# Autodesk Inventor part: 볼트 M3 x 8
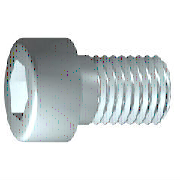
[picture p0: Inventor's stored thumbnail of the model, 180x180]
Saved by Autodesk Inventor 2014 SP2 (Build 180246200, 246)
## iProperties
Created: 2012-02
Part Number: 볼트 M3 x 8
Material: 스테인리스강
Description: 6각 소켓 머리 캡 나사
Document SubType Name: Modeling
Standard: ISO 4762
Designer: mduedu
Standard Revision: Fourth edition 2004-03-01
Standards Organization: ISO
Language: ko-KR
Size Designation: M3 x 8
Categories: <MemberInstance><Categories><Category DisplayName="조임쇠" InternalName="e4da775c-781d-43d5-af7c-5136215cf5a6" Mnemonic="FSTN"><Category DisplayName="볼트" InternalN
Density: 8.08 g/cm^3
Appearance: 반광택
IsCustomPart: 0
Author: mduedu
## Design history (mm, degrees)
sketch "스케치1"
  geometry: L1 (-0.867, 0)-(8, 0); L2 (8, 0)-(8, 1.5); L3 (8, 1.5)-(1.25, 1.5); L4 (1.25, 1.5)-(0.943, 1.5); L5 (0.943, 1.5)-(0, 1.5); L6 (0, 1.5)-(0, 2.75); L7 (0, 2.75)-(-3, 2.75); L8 (-3, 2.75)-(-3, 1.443); L9 (-3, 1.443)-(-1.7, 1.443); L10 (-1.7, 1.443)-(-0.867, 0); L11 (-5.2, 0)-(10.2, 0) reference; L12 (0, -0.55)-(0, 3.3) reference; L13 (1.25, 1.5)-(0, 1.5)
  constraints: 22 end point, 6 parallel, 2 collinear, 2 perpendicular, 1 horizontal, 1 point on line
  dimensions: "d1" = 6.75 distance from line of L3.end L2 (= GEL); "d2" = 0.30683 distance of L4.end L3.end (computed from GAL); "d3" = 3 distance between parallel lines of L8 L6 (= KOH); "d4" = 1.3 distance of L8.end L9.end (= INTI); "d5" = 60 deg angle of L10 L1; "d6" = 3 diameter of L3 L1 (= GD); "d7" = 3 diameter of L5 L1 (= BDM); "d8" = 2.88675 diameter of L9 L1 (= 1.1547 x SW); "d9" = 5.5 diameter of L7 L1 (= KOD); "d26" = 8 distance between parallel lines of L12 L2 (= NLG)
revolve "본체" sketch "스케치1" stored, may be unused: angle "d10" = 90 deg
sketch "스케치2"
  geometry: L1 (0, -3.85)-(0, 3.85) reference; L2 (-3.85, 0)-(3.85, 0) reference; L3 (1.443, 0)-(0.722, -1.25); L4 (0.722, -1.25)-(-0.722, -1.25); L5 (-0.722, -1.25)-(-1.443, 0); L6 (-1.443, 0)-(-0.722, 1.25); L7 (-0.722, 1.25)-(0.722, 1.25); L8 (0.722, 1.25)-(1.443, 0); 2 further points
  constraints: 12 end point, 1 coincident, 1 horizontal alignment, 1 point on line, 12 other
extrude "슬롯" join sketch "스케치2" stored distance "d11" = 10; taper "d12" = 0 deg
workplane "Work Plane1"
fillet "Fillet2" dims "d30" = 0.1 (= R)
body "Solid1"
fillet "모깎기1" dims "d17" = 0.3 (= RR)
feature "스레드" dims "d13" = 6.75 (= GEL), "d14" = 0
chamfer "모따기1" distance "d15" = 0.30673 (= -0.5 x SPD + 0.5 x GD); stored, may be unused: second distance "d16" = 0.30673 (= GUL), angle "d27" = 45 deg
other parameters: "GD" = 3 [user parameter; used in 2 equation terms], "NLG" = 8 [user parameter; used in 1 equation term], "GEL" = 6.75 [user parameter; used in 2 equation terms], "KOD" = 5.5 [user parameter; used in 1 equation term], "KOH" = 3 [user parameter; used in 1 equation term], "INTI" = 1.3 [user parameter; used in 1 equation term], "GAL" = 0.30673 (= 0.61345 x PTC) [user parameter; used in 1 equation term], "GUL" = 0.30673 (= 0.61345 x PTC) [user parameter; used in 1 equation term], "BDM" = 3 (= NND) [user parameter; used in 1 equation term], "SW" = 2.5 [user parameter; used in 2 equation terms], "RR" = 0.3 [user parameter; used in 1 equation term], "SPD" = 2.38655 (= NND - 1.2269 x PTC) [user parameter; used in 1 equation term], "d19" = 0, "d28" = 0, "d29" = 0, "R" = 0.1 [user parameter; used in 1 equation term], "TOA" = 30 deg [user parameter], "GD1" = 2.38655 (= THREADDIA - 1.2269 x PTC) [user parameter], "THREADDIA" = 3 [user parameter; used in 1 equation term], "FAWI" = 45 deg [user parameter], "PTC" = 0.5 [user parameter; used in 5 equation terms], "NND" = 3 [user parameter; used in 2 equation terms], "E0" = 2.8875 (= 1.155 x SW) [user parameter]
